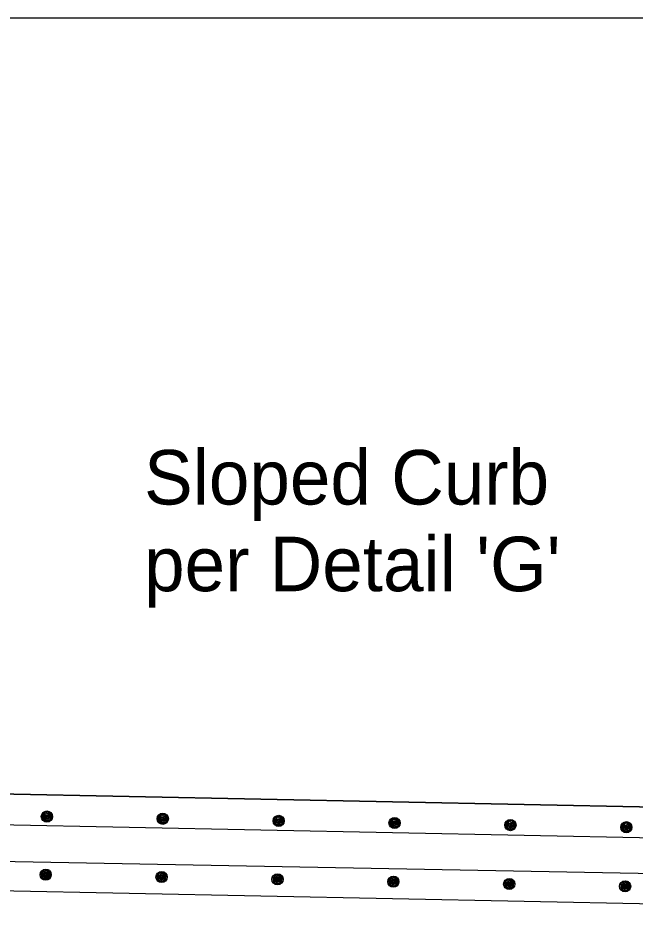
# Model space of a CAD drawing. Extents: x -2134934 to -2124557, y -2139046 to -2134021.
# Drawn here: x -2127032.7 to -2126851.4, y -2137299.6 to -2137035.9 of the extents above; entities that cross this region are included whole.
import ezdxf

# ---------------------------------------------------------------- set-up
doc = ezdxf.new("R2010")
doc.units = 0
for name, color, linetype in [('BridgeSuperStructureExisting', 7, 'Continuous'), ('dsnAlignmentStation', 7, 'Continuous'), ('dsnStdLabel', 7, 'Continuous')]:
    doc.layers.add(name, color=color, linetype=linetype)

msp = doc.modelspace()

# ---------------------------------------------------------------- linework, layer by layer
at = {"layer": 'BridgeSuperStructureExisting'}
for p, q in [((-2126773.45, -2137269.05), (-2127483.71, -2137254.79)), ((-2127483.71, -2137254.79), (-2126773.45, -2137269.05)), ((-2127483.71, -2137263.74), (-2126752.01, -2137278.43)), ((-2127484.27, -2137283.15), (-2126735.17, -2137298.18)), ((-2127483.14, -2137283.17), (-2126735.17, -2137298.18))]:
    msp.add_line(p, q, dxfattribs=at)
for points in [[(-2127025.68, -2137270.43), (-2127025.41, -2137269.88), (-2127025.11, -2137269.02), (-2127024.22, -2137268.89), (-2127023.45, -2137269.04), (-2127022.76, -2137269.62), (-2127022.86, -2137270.45), (-2127023.02, -2137271.31), (-2127023.73, -2137271.7), (-2127024.46, -2137271.75), (-2127025.4, -2137271.2), (-2127025.45, -2137270.56), (-2127025.2, -2137269.7), (-2127024.62, -2137269.01), (-2127023.8, -2137269.06), (-2127023.15, -2137269.64), (-2127023.11, -2137270.43), (-2127023.31, -2137271.29), (-2127023.8, -2137271.4), (-2127024.4, -2137271.56), (-2127025.1, -2137271.12), (-2127025.06, -2137270.49), (-2127024.91, -2137269.77), (-2127024.49, -2137269.26), (-2127023.78, -2137269.55), (-2127023.38, -2137270.11), (-2127023.38, -2137270.85), (-2127023.78, -2137271.01), (-2127024.23, -2137271.23), (-2127024.79, -2137270.85), (-2127024.9, -2137270.31), (-2127024.63, -2137269.84), (-2127024.09, -2137269.82), (-2127023.72, -2137270.09), (-2127023.6, -2137270.59), (-2127023.82, -2137270.82), (-2127024.12, -2137270.94), (-2127024.54, -2137270.67), (-2127024.61, -2137270.33), (-2127024.39, -2137270), (-2127024.1, -2137270.07), (-2127023.93, -2137270.32), (-2127023.95, -2137270.66), (-2127024.19, -2137270.65), (-2127024.32, -2137270.34)], [(-2126991.65, -2137271.06), (-2126991.38, -2137270.5), (-2126991.08, -2137269.65), (-2126990.19, -2137269.51), (-2126989.42, -2137269.66), (-2126988.73, -2137270.25), (-2126988.83, -2137271.07), (-2126988.99, -2137271.94), (-2126989.7, -2137272.33), (-2126990.43, -2137272.37), (-2126991.37, -2137271.83), (-2126991.42, -2137271.18), (-2126991.17, -2137270.33), (-2126990.59, -2137269.63), (-2126989.76, -2137269.69), (-2126989.12, -2137270.27), (-2126989.08, -2137271.05), (-2126989.28, -2137271.92), (-2126989.77, -2137272.03), (-2126990.37, -2137272.18), (-2126991.07, -2137271.75), (-2126991.03, -2137271.12), (-2126990.88, -2137270.39), (-2126990.46, -2137269.89), (-2126989.74, -2137270.18), (-2126989.35, -2137270.74), (-2126989.35, -2137271.47), (-2126989.75, -2137271.64), (-2126990.2, -2137271.85), (-2126990.76, -2137271.48), (-2126990.87, -2137270.93), (-2126990.59, -2137270.46), (-2126990.05, -2137270.45), (-2126989.68, -2137270.72), (-2126989.57, -2137271.21), (-2126989.78, -2137271.44), (-2126990.08, -2137271.57), (-2126990.51, -2137271.3), (-2126990.58, -2137270.95), (-2126990.36, -2137270.62), (-2126990.07, -2137270.69), (-2126989.89, -2137270.95), (-2126989.92, -2137271.29), (-2126990.16, -2137271.27), (-2126990.29, -2137270.97)], [(-2126957.61, -2137271.68), (-2126957.34, -2137271.13), (-2126957.04, -2137270.28), (-2126956.16, -2137270.14), (-2126955.38, -2137270.29), (-2126954.69, -2137270.87), (-2126954.8, -2137271.7), (-2126954.95, -2137272.56), (-2126955.66, -2137272.95), (-2126956.4, -2137273), (-2126957.33, -2137272.45), (-2126957.39, -2137271.81), (-2126957.14, -2137270.95), (-2126956.55, -2137270.26), (-2126955.73, -2137270.32), (-2126955.09, -2137270.89), (-2126955.04, -2137271.68), (-2126955.24, -2137272.54), (-2126955.74, -2137272.65), (-2126956.33, -2137272.81), (-2126957.03, -2137272.37), (-2126957, -2137271.74), (-2126956.85, -2137271.02), (-2126956.42, -2137270.51), (-2126955.71, -2137270.8), (-2126955.31, -2137271.37), (-2126955.31, -2137272.1), (-2126955.72, -2137272.27), (-2126956.16, -2137272.48), (-2126956.72, -2137272.1), (-2126956.84, -2137271.56), (-2126956.56, -2137271.09), (-2126956.02, -2137271.07), (-2126955.65, -2137271.34), (-2126955.54, -2137271.84), (-2126955.75, -2137272.07), (-2126956.05, -2137272.19), (-2126956.47, -2137271.92), (-2126956.54, -2137271.58), (-2126956.33, -2137271.25), (-2126956.04, -2137271.32), (-2126955.86, -2137271.57), (-2126955.88, -2137271.92), (-2126956.13, -2137271.9), (-2126956.25, -2137271.6)], [(-2126923.58, -2137272.31), (-2126923.31, -2137271.76), (-2126923.01, -2137270.9), (-2126922.12, -2137270.77), (-2126921.35, -2137270.92), (-2126920.66, -2137271.5), (-2126920.76, -2137272.32), (-2126920.92, -2137273.19), (-2126921.63, -2137273.58), (-2126922.36, -2137273.63), (-2126923.3, -2137273.08), (-2126923.35, -2137272.44), (-2126923.1, -2137271.58), (-2126922.52, -2137270.88), (-2126921.7, -2137270.95), (-2126921.05, -2137271.52), (-2126921.01, -2137272.31), (-2126921.21, -2137273.17), (-2126921.7, -2137273.28), (-2126922.3, -2137273.44), (-2126923, -2137273), (-2126922.96, -2137272.37), (-2126922.81, -2137271.65), (-2126922.39, -2137271.14), (-2126921.68, -2137271.43), (-2126921.28, -2137271.99), (-2126921.28, -2137272.72), (-2126921.68, -2137272.89), (-2126922.13, -2137273.11), (-2126922.69, -2137272.73), (-2126922.8, -2137272.18), (-2126922.53, -2137271.71), (-2126921.99, -2137271.7), (-2126921.62, -2137271.97), (-2126921.5, -2137272.47), (-2126921.72, -2137272.7), (-2126922.02, -2137272.82), (-2126922.44, -2137272.55), (-2126922.51, -2137272.2), (-2126922.29, -2137271.88), (-2126922, -2137271.94), (-2126921.83, -2137272.2), (-2126921.85, -2137272.54), (-2126922.09, -2137272.53), (-2126922.22, -2137272.23)], [(-2126889.55, -2137272.93), (-2126889.28, -2137272.39), (-2126888.97, -2137271.53), (-2126888.09, -2137271.39), (-2126887.32, -2137271.54), (-2126886.62, -2137272.13), (-2126886.73, -2137272.95), (-2126886.89, -2137273.82), (-2126887.59, -2137274.21), (-2126888.33, -2137274.26), (-2126889.27, -2137273.7), (-2126889.32, -2137273.07), (-2126889.07, -2137272.2), (-2126888.48, -2137271.51), (-2126887.66, -2137271.57), (-2126887.02, -2137272.15), (-2126886.97, -2137272.93), (-2126887.18, -2137273.79), (-2126887.67, -2137273.91), (-2126888.27, -2137274.06), (-2126888.97, -2137273.62), (-2126888.92, -2137273), (-2126888.78, -2137272.27), (-2126888.36, -2137271.76), (-2126887.64, -2137272.06), (-2126887.24, -2137272.62), (-2126887.25, -2137273.35), (-2126887.64, -2137273.52), (-2126888.1, -2137273.73), (-2126888.66, -2137273.35), (-2126888.76, -2137272.81), (-2126888.49, -2137272.34), (-2126887.95, -2137272.33), (-2126887.58, -2137272.59), (-2126887.47, -2137273.09), (-2126887.68, -2137273.32), (-2126887.98, -2137273.45), (-2126888.4, -2137273.18), (-2126888.47, -2137272.83), (-2126888.26, -2137272.5), (-2126887.97, -2137272.57), (-2126887.79, -2137272.83), (-2126887.82, -2137273.17), (-2126888.06, -2137273.15), (-2126888.18, -2137272.85)], [(-2126855.51, -2137273.56), (-2126855.24, -2137273.01), (-2126854.94, -2137272.15), (-2126854.06, -2137272.02), (-2126853.28, -2137272.17), (-2126852.59, -2137272.75), (-2126852.7, -2137273.57), (-2126852.85, -2137274.44), (-2126853.56, -2137274.83), (-2126854.3, -2137274.88), (-2126855.23, -2137274.33), (-2126855.29, -2137273.69), (-2126855.04, -2137272.83), (-2126854.45, -2137272.14), (-2126853.63, -2137272.2), (-2126852.98, -2137272.78), (-2126852.94, -2137273.56), (-2126853.14, -2137274.42), (-2126853.64, -2137274.54), (-2126854.23, -2137274.69), (-2126854.93, -2137274.25), (-2126854.89, -2137273.62), (-2126854.75, -2137272.9), (-2126854.32, -2137272.39), (-2126853.61, -2137272.68), (-2126853.21, -2137273.24), (-2126853.21, -2137273.98), (-2126853.61, -2137274.14), (-2126854.06, -2137274.36), (-2126854.62, -2137273.98), (-2126854.74, -2137273.44), (-2126854.46, -2137272.97), (-2126853.92, -2137272.96), (-2126853.55, -2137273.22), (-2126853.44, -2137273.72), (-2126853.65, -2137273.95), (-2126853.95, -2137274.08), (-2126854.37, -2137273.8), (-2126854.44, -2137273.45), (-2126854.22, -2137273.13), (-2126853.94, -2137273.19), (-2126853.76, -2137273.45), (-2126853.78, -2137273.79), (-2126854.03, -2137273.78), (-2126854.15, -2137273.48)], [(-2127022.99, -2137287.54), (-2127023.24, -2137286.98), (-2127023.51, -2137286.12), (-2127024.39, -2137285.95), (-2127025.17, -2137286.07), (-2127025.88, -2137286.62), (-2127025.81, -2137287.45), (-2127025.68, -2137288.32), (-2127024.99, -2137288.74), (-2127024.26, -2137288.82), (-2127023.3, -2137288.3), (-2127023.22, -2137287.67), (-2127023.44, -2137286.79), (-2127024, -2137286.08), (-2127024.82, -2137286.1), (-2127025.49, -2137286.66), (-2127025.56, -2137287.44), (-2127025.39, -2137288.31), (-2127024.9, -2137288.44), (-2127024.31, -2137288.62), (-2127023.6, -2137288.21), (-2127023.61, -2137287.58), (-2127023.73, -2137286.85), (-2127024.14, -2137286.33), (-2127024.86, -2137286.59), (-2127025.28, -2137287.14), (-2127025.31, -2137287.87), (-2127024.91, -2137288.05), (-2127024.47, -2137288.29), (-2127023.9, -2137287.93), (-2127023.77, -2137287.39), (-2127024.02, -2137286.91), (-2127024.56, -2137286.87), (-2127024.94, -2137287.13), (-2127025.07, -2137287.62), (-2127024.87, -2137287.86), (-2127024.58, -2137287.99), (-2127024.14, -2137287.74), (-2127024.06, -2137287.4), (-2127024.26, -2137287.06), (-2127024.55, -2137287.12), (-2127024.74, -2137287.37), (-2127024.73, -2137287.71), (-2127024.49, -2137287.7), (-2127024.35, -2137287.4)], [(-2126988.96, -2137288.23), (-2126989.21, -2137287.67), (-2126989.48, -2137286.8), (-2126990.36, -2137286.63), (-2126991.13, -2137286.75), (-2126991.85, -2137287.3), (-2126991.78, -2137288.13), (-2126991.65, -2137289), (-2126990.96, -2137289.42), (-2126990.23, -2137289.5), (-2126989.27, -2137288.98), (-2126989.19, -2137288.35), (-2126989.41, -2137287.48), (-2126989.97, -2137286.76), (-2126990.79, -2137286.78), (-2126991.46, -2137287.34), (-2126991.53, -2137288.12), (-2126991.36, -2137289), (-2126990.87, -2137289.13), (-2126990.28, -2137289.3), (-2126989.56, -2137288.89), (-2126989.58, -2137288.26), (-2126989.7, -2137287.53), (-2126990.1, -2137287.01), (-2126990.83, -2137287.28), (-2126991.25, -2137287.82), (-2126991.28, -2137288.55), (-2126990.88, -2137288.73), (-2126990.44, -2137288.97), (-2126989.86, -2137288.61), (-2126989.74, -2137288.07), (-2126989.99, -2137287.59), (-2126990.53, -2137287.56), (-2126990.91, -2137287.81), (-2126991.04, -2137288.3), (-2126990.84, -2137288.54), (-2126990.54, -2137288.68), (-2126990.11, -2137288.42), (-2126990.03, -2137288.08), (-2126990.23, -2137287.74), (-2126990.52, -2137287.8), (-2126990.71, -2137288.05), (-2126990.7, -2137288.39), (-2126990.45, -2137288.38), (-2126990.32, -2137288.08)], [(-2126954.93, -2137288.91), (-2126955.18, -2137288.35), (-2126955.45, -2137287.48), (-2126956.32, -2137287.31), (-2126957.1, -2137287.43), (-2126957.82, -2137287.99), (-2126957.74, -2137288.82), (-2126957.62, -2137289.68), (-2126956.93, -2137290.1), (-2126956.2, -2137290.18), (-2126955.24, -2137289.67), (-2126955.16, -2137289.03), (-2126955.38, -2137288.16), (-2126955.93, -2137287.45), (-2126956.76, -2137287.47), (-2126957.43, -2137288.02), (-2126957.5, -2137288.81), (-2126957.33, -2137289.68), (-2126956.84, -2137289.81), (-2126956.25, -2137289.99), (-2126955.53, -2137289.58), (-2126955.55, -2137288.94), (-2126955.67, -2137288.22), (-2126956.07, -2137287.7), (-2126956.79, -2137287.96), (-2126957.22, -2137288.51), (-2126957.24, -2137289.24), (-2126956.85, -2137289.42), (-2126956.41, -2137289.65), (-2126955.83, -2137289.29), (-2126955.7, -2137288.75), (-2126955.96, -2137288.27), (-2126956.5, -2137288.24), (-2126956.88, -2137288.49), (-2126957.01, -2137288.99), (-2126956.81, -2137289.22), (-2126956.51, -2137289.36), (-2126956.08, -2137289.11), (-2126956, -2137288.76), (-2126956.2, -2137288.43), (-2126956.49, -2137288.48), (-2126956.67, -2137288.73), (-2126956.66, -2137289.07), (-2126956.42, -2137289.07), (-2126956.29, -2137288.77)], [(-2126920.89, -2137289.59), (-2126921.14, -2137289.03), (-2126921.41, -2137288.17), (-2126922.29, -2137287.99), (-2126923.07, -2137288.11), (-2126923.78, -2137288.67), (-2126923.71, -2137289.5), (-2126923.59, -2137290.37), (-2126922.9, -2137290.79), (-2126922.16, -2137290.86), (-2126921.2, -2137290.35), (-2126921.13, -2137289.71), (-2126921.34, -2137288.84), (-2126921.9, -2137288.13), (-2126922.72, -2137288.15), (-2126923.39, -2137288.71), (-2126923.46, -2137289.49), (-2126923.3, -2137290.36), (-2126922.81, -2137290.49), (-2126922.22, -2137290.67), (-2126921.5, -2137290.26), (-2126921.51, -2137289.63), (-2126921.63, -2137288.9), (-2126922.04, -2137288.38), (-2126922.76, -2137288.64), (-2126923.18, -2137289.19), (-2126923.21, -2137289.92), (-2126922.81, -2137290.1), (-2126922.37, -2137290.33), (-2126921.8, -2137289.97), (-2126921.67, -2137289.44), (-2126921.92, -2137288.96), (-2126922.46, -2137288.92), (-2126922.84, -2137289.18), (-2126922.98, -2137289.67), (-2126922.77, -2137289.91), (-2126922.48, -2137290.04), (-2126922.04, -2137289.79), (-2126921.96, -2137289.44), (-2126922.16, -2137289.11), (-2126922.46, -2137289.17), (-2126922.64, -2137289.41), (-2126922.63, -2137289.76), (-2126922.39, -2137289.75), (-2126922.25, -2137289.45)], [(-2126886.86, -2137290.27), (-2126887.11, -2137289.72), (-2126887.38, -2137288.85), (-2126888.26, -2137288.68), (-2126889.04, -2137288.8), (-2126889.75, -2137289.35), (-2126889.68, -2137290.18), (-2126889.55, -2137291.05), (-2126888.86, -2137291.47), (-2126888.13, -2137291.55), (-2126887.17, -2137291.03), (-2126887.09, -2137290.4), (-2126887.31, -2137289.53), (-2126887.87, -2137288.81), (-2126888.69, -2137288.84), (-2126889.36, -2137289.39), (-2126889.43, -2137290.18), (-2126889.26, -2137291.04), (-2126888.77, -2137291.18), (-2126888.18, -2137291.35), (-2126887.47, -2137290.95), (-2126887.48, -2137290.31), (-2126887.6, -2137289.59), (-2126888, -2137289.06), (-2126888.73, -2137289.32), (-2126889.15, -2137289.87), (-2126889.18, -2137290.6), (-2126888.78, -2137290.79), (-2126888.34, -2137291.02), (-2126887.77, -2137290.66), (-2126887.63, -2137290.12), (-2126887.89, -2137289.64), (-2126888.43, -2137289.61), (-2126888.81, -2137289.86), (-2126888.94, -2137290.36), (-2126888.74, -2137290.59), (-2126888.45, -2137290.73), (-2126888.01, -2137290.47), (-2126887.93, -2137290.13), (-2126888.13, -2137289.79), (-2126888.42, -2137289.85), (-2126888.61, -2137290.1), (-2126888.6, -2137290.44), (-2126888.36, -2137290.43), (-2126888.22, -2137290.14)], [(-2126852.83, -2137290.96), (-2126853.08, -2137290.4), (-2126853.34, -2137289.53), (-2126854.23, -2137289.36), (-2126855, -2137289.48), (-2126855.72, -2137290.04), (-2126855.65, -2137290.86), (-2126855.52, -2137291.74), (-2126854.83, -2137292.16), (-2126854.1, -2137292.23), (-2126853.14, -2137291.71), (-2126853.06, -2137291.08), (-2126853.28, -2137290.21), (-2126853.84, -2137289.5), (-2126854.66, -2137289.52), (-2126855.32, -2137290.08), (-2126855.4, -2137290.86), (-2126855.23, -2137291.73), (-2126854.74, -2137291.86), (-2126854.15, -2137292.04), (-2126853.43, -2137291.63), (-2126853.45, -2137290.99), (-2126853.57, -2137290.27), (-2126853.97, -2137289.74), (-2126854.7, -2137290.01), (-2126855.12, -2137290.56), (-2126855.14, -2137291.29), (-2126854.75, -2137291.47), (-2126854.31, -2137291.7), (-2126853.73, -2137291.34), (-2126853.6, -2137290.8), (-2126853.86, -2137290.33), (-2126854.4, -2137290.29), (-2126854.78, -2137290.54), (-2126854.91, -2137291.03), (-2126854.71, -2137291.27), (-2126854.41, -2137291.41), (-2126853.98, -2137291.15), (-2126853.9, -2137290.81), (-2126854.1, -2137290.47), (-2126854.39, -2137290.53), (-2126854.58, -2137290.78), (-2126854.57, -2137291.12), (-2126854.32, -2137291.12), (-2126854.19, -2137290.82)]]:
    msp.add_lwpolyline(points, dxfattribs=at)
for centre in [(-2127024.16, -2137270.36), (-2126990.12, -2137270.99), (-2126956.09, -2137271.61), (-2126922.06, -2137272.24), (-2126888.02, -2137272.87), (-2126853.99, -2137273.49), (-2127024.51, -2137287.42), (-2126990.48, -2137288.1), (-2126956.44, -2137288.78), (-2126922.41, -2137289.47), (-2126888.38, -2137290.15), (-2126854.35, -2137290.83)]:
    msp.add_circle(centre, 1.65, dxfattribs=at)
at = {"layer": 'dsnAlignmentStation'}
msp.add_lwpolyline([(-2127734.44, -2137035.95), (-2124599.45, -2137035.95), (-2124599.45, -2139045.94), (-2127734.44, -2139045.94)], close=True, dxfattribs=at)
at = {"layer": 'dsnStdLabel'}
msp.add_line((-2126752.19, -2137288.89), (-2127483.74, -2137275.34), dxfattribs=at)

# ---------------------------------------------------------------- texts
for s, p in [('Sloped Curb', (-2126995.62, -2137178.76)), ("per Detail 'G'", (-2126995.62, -2137204.21))]:
    msp.add_text(s, height=16, dxfattribs=at).set_placement(p)

doc.saveas('drawing.dxf')
